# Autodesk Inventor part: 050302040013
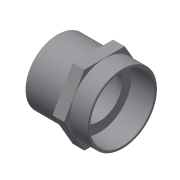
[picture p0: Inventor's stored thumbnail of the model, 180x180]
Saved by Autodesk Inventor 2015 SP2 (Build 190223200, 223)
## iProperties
Created: 2017-10
Part Number: 050302040013
Material: Generic
Description: PLASSON ADAPTOR SOCKET M.F. 40-1.1/4" CEM-THR
Document SubType Name: Modeling
Designer: KIM
Density: 1 g/cm^3
Appearance: Default
Author: KIM
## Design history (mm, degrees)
derived "050302.ipt"
feature "Solid1::050302.ipt"
tag "TaggingFeature1"
body "Solid1"
other parameters: "d0" = 63, "d3" = 38.952, "d4" = 28, "d8" = 46, "d13" = 0, "d14" = 0.4, "d16" = 16, "d17" = 26, "d18" = 24, "d20" = 32, "G_" = 38.952, "B_" = 16, "L_" = 26, "H_" = 63
